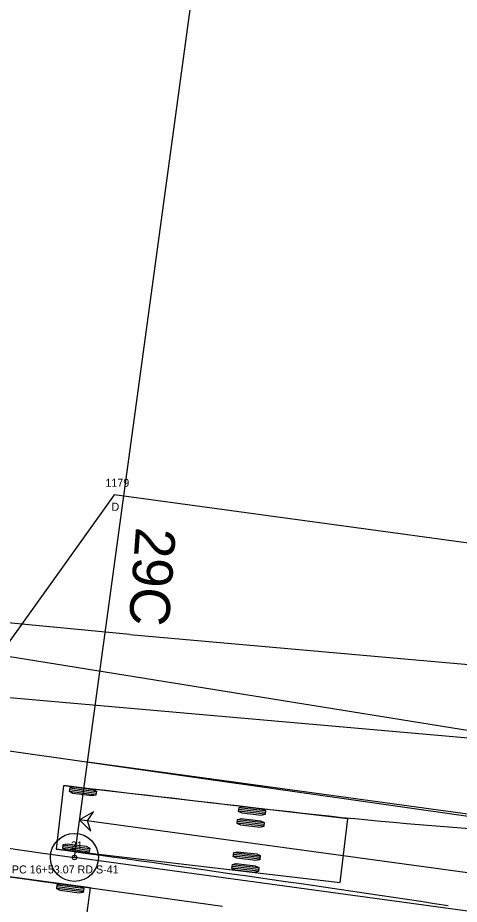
# Model space of a CAD drawing. Extents: x 1812113 to 1819860, y 1177290 to 1181185.
# Drawn here: x 1813531.1 to 1813586.4, y 1178765.6 to 1178876.4 of the extents above; entities that cross this region are included whole.
import ezdxf

# ---------------------------------------------------------------- set-up
doc = ezdxf.new("R2010")
doc.units = 0
for name, color, linetype in [('RD_EX_Driveway', 7, 'Continuous'), ('RD_EX_Driveway_txCode', 7, 'Continuous'), ('RD_EX_Road', 7, 'Continuous'), ('RD_EX_RW', 7, 'Continuous'), ('RD_HC_CL', 7, 'Continuous'), ('RD_HC_Data', 7, 'Continuous'), ('RD_HC_txCode', 7, 'Continuous'), ('RD_PD_ALT1_TrvlWay', 7, 'Continuous'), ('RD_PD_CstnLmt', 7, 'Continuous'), ('RD_Sketch5', 7, 'Continuous'), ('RD_Sketch9', 7, 'Continuous'), ('RD_SMD_Locator', 7, 'Continuous')]:
    doc.layers.add(name, color=color, linetype=linetype)

msp = doc.modelspace()

# ---------------------------------------------------------------- linework, layer by layer
at = {"layer": 'RD_EX_Driveway'}
for points in [[(1813615.6, 1178795.77), (1813617.78, 1178806.55), (1813543.17, 1178816.74), (1813525.31, 1178791.79)], [(1813638.42, 1178791.25), (1813630.13, 1178786.38), (1813613.34, 1178784.52), (1813588.43, 1178786.24), (1813525.31, 1178791.79), (1813522.62, 1178785.74)]]:
    msp.add_lwpolyline(points, dxfattribs=at)
at = {"layer": 'RD_EX_Road'}
msp.add_line((1813596.09, 1178775.31), (1813522.62, 1178785.74), dxfattribs=at)
at = {"layer": 'RD_EX_RW'}
msp.add_line((1813632.03, 1178780.07), (1813400.47, 1178817.38), dxfattribs=at)
at = {"layer": 'RD_HC_CL'}
msp.add_line((1813641.28, 1178757.34), (1813538.22, 1178771.42), dxfattribs=at)
msp.add_arc((1813766.93, 1180445.18), 1689.31, 243.58271, 262.2191, dxfattribs=at)
at = {"layer": 'RD_HC_Data'}
msp.add_line((1813538.22, 1178771.42), (1813553.17, 1178880.85), dxfattribs=at)
for radius in [3, 0.282]:
    msp.add_circle((1813538.22, 1178771.42), radius, dxfattribs=at)
at = {"layer": 'RD_PD_ALT1_TrvlWay'}
msp.add_line((1813598.75, 1178775.26), (1813539.84, 1178783.31), dxfattribs=at)
at = {"layer": 'RD_PD_CstnLmt'}
for q in [(1813496.03, 1178803.9), (1813594.99, 1178794.88)]:
    msp.add_line((1813545.13, 1178799.29), q, dxfattribs=at)
at = {"layer": 'RD_Sketch5'}
for p, q in [((1813540.22, 1178767.61), (1813504.75, 1178772.46)), ((1813539.31, 1178767.11), (1813536.01, 1178767.56)), ((1813539.34, 1178767.31), (1813536.04, 1178767.76)), ((1813539.37, 1178767.52), (1813536.07, 1178767.97)), ((1813539.14, 1178759.69), (1813540.22, 1178767.61)), ((1813540.22, 1178767.61), (1813540.22, 1178767.61))]:
    msp.add_line(p, q, dxfattribs=at)
msp.add_lwpolyline([(1813529.58, 1178769.07), (1813533.13, 1178768.58), (1813536.68, 1178768.1), (1813540.22, 1178767.61), (1813540.22, 1178767.61), (1813543.53, 1178767.16), (1813546.84, 1178766.71), (1813550.14, 1178766.26), (1813553.45, 1178765.81), (1813556.76, 1178765.35)], dxfattribs=at)
msp.add_lwpolyline([(1813539.38, 1178767.57), (1813539.3, 1178767.06), (1813538.82, 1178766.96), (1813536.44, 1178767.29), (1813536, 1178767.51), (1813536.07, 1178768.02), (1813536.56, 1178768.11), (1813538.93, 1178767.79)], close=True, dxfattribs=at)
at = {"layer": 'RD_Sketch9'}
for p, q in [((1813536.84, 1178780.39), (1813535.92, 1178772.44)), ((1813572.4, 1178776.24), (1813536.84, 1178780.39)), ((1813537.61, 1178779.7), (1813540.91, 1178779.25)), ((1813537.63, 1178779.91), (1813540.94, 1178779.46)), ((1813537.66, 1178780.12), (1813540.96, 1178779.66)), ((1813562.09, 1178777.02), (1813558.78, 1178777.41)), ((1813562.11, 1178777.23), (1813558.8, 1178777.62)), ((1813562.07, 1178776.82), (1813558.75, 1178777.2)), ((1813571.47, 1178768.3), (1813572.4, 1178776.24)), ((1813604.8, 1178767.12), (1813538.86, 1178776.13)), ((1813561.89, 1178775.33), (1813558.58, 1178775.71)), ((1813561.92, 1178775.53), (1813558.6, 1178775.92)), ((1813561.94, 1178775.74), (1813558.63, 1178776.13)), ((1813536.82, 1178773), (1813540.12, 1178772.55)), ((1813535.92, 1178772.44), (1813571.47, 1178768.3)), ((1813535.92, 1178772.44), (1813535.92, 1178772.44)), ((1813536.76, 1178772.59), (1813540.06, 1178772.14)), ((1813536.79, 1178772.79), (1813540.09, 1178772.34)), ((1813561.43, 1178771.4), (1813558.12, 1178771.78)), ((1813561.46, 1178771.6), (1813558.15, 1178771.99)), ((1813561.41, 1178771.19), (1813558.1, 1178771.58)), ((1813561.23, 1178769.7), (1813557.92, 1178770.09)), ((1813561.26, 1178769.91), (1813557.95, 1178770.29)), ((1813561.28, 1178770.11), (1813557.97, 1178770.5))]:
    msp.add_line(p, q, dxfattribs=at)
for points in [[(1813587.65, 1178775.01), (1813586.08, 1178775.12), (1813584.51, 1178775.23), (1813582.93, 1178775.36), (1813581.34, 1178775.49), (1813579.74, 1178775.62), (1813578.14, 1178775.77), (1813576.53, 1178775.91), (1813574.91, 1178776.07), (1813573.3, 1178776.23), (1813571.68, 1178776.39), (1813570.05, 1178776.56), (1813568.42, 1178776.74), (1813566.79, 1178776.92), (1813565.16, 1178777.1), (1813563.53, 1178777.28), (1813561.89, 1178777.47), (1813560.25, 1178777.66), (1813558.61, 1178777.85), (1813556.97, 1178778.04), (1813555.32, 1178778.23), (1813553.68, 1178778.42), (1813552.03, 1178778.62), (1813550.39, 1178778.81), (1813548.74, 1178779), (1813547.09, 1178779.19), (1813545.44, 1178779.39), (1813543.79, 1178779.58), (1813542.13, 1178779.77), (1813540.48, 1178779.96), (1813538.83, 1178780.16), (1813537.17, 1178780.35), (1813536.84, 1178780.39)], [(1813584.96, 1178765.38), (1813583.25, 1178765.64), (1813581.54, 1178765.9), (1813579.83, 1178766.16), (1813578.13, 1178766.41), (1813576.43, 1178766.66), (1813574.73, 1178766.91), (1813573.04, 1178767.16), (1813571.35, 1178767.41), (1813569.67, 1178767.66), (1813567.98, 1178767.9), (1813566.3, 1178768.15), (1813564.62, 1178768.39), (1813562.94, 1178768.63), (1813561.26, 1178768.87), (1813559.59, 1178769.11), (1813557.92, 1178769.35), (1813556.24, 1178769.59), (1813554.57, 1178769.83), (1813552.9, 1178770.06), (1813551.23, 1178770.3), (1813549.57, 1178770.53), (1813547.9, 1178770.77), (1813546.23, 1178771), (1813544.57, 1178771.24), (1813542.9, 1178771.47), (1813541.24, 1178771.7), (1813539.57, 1178771.93), (1813537.91, 1178772.17), (1813536.25, 1178772.4), (1813535.92, 1178772.44)]]:
    msp.add_lwpolyline(points, dxfattribs=at)
for points in [[(1813537.6, 1178779.65), (1813537.67, 1178780.17), (1813538.15, 1178780.26), (1813540.53, 1178779.93), (1813540.97, 1178779.72), (1813540.9, 1178779.2), (1813540.42, 1178779.11), (1813538.04, 1178779.43)], [(1813562.12, 1178777.28), (1813562.06, 1178776.77), (1813561.58, 1178776.66), (1813559.19, 1178776.94), (1813558.75, 1178777.15), (1813558.81, 1178777.67), (1813559.29, 1178777.77), (1813561.67, 1178777.49)], [(1813538.86, 1178776.13), (1813540.27, 1178774.7), (1813539.85, 1178775.99), (1813540.6, 1178777.12)], [(1813561.95, 1178775.79), (1813561.89, 1178775.28), (1813561.4, 1178775.18), (1813559.02, 1178775.45), (1813558.57, 1178775.66), (1813558.63, 1178776.18), (1813559.12, 1178776.28), (1813561.5, 1178776)], [(1813536.75, 1178772.54), (1813536.82, 1178773.05), (1813537.31, 1178773.14), (1813539.68, 1178772.82), (1813540.13, 1178772.6), (1813540.05, 1178772.08), (1813539.57, 1178771.99), (1813537.19, 1178772.32)], [(1813561.46, 1178771.65), (1813561.4, 1178771.14), (1813560.92, 1178771.04), (1813558.54, 1178771.31), (1813558.09, 1178771.52), (1813558.15, 1178772.04), (1813558.63, 1178772.14), (1813561.02, 1178771.86)], [(1813561.29, 1178770.16), (1813561.23, 1178769.65), (1813560.75, 1178769.55), (1813558.36, 1178769.82), (1813557.92, 1178770.03), (1813557.98, 1178770.55), (1813558.46, 1178770.65), (1813560.84, 1178770.37)]]:
    msp.add_lwpolyline(points, close=True, dxfattribs=at)
at = {"layer": 'RD_SMD_Locator'}
for centre in [(1813543.17, 1178816.74), (1813538.22, 1178771.42)]:
    msp.add_circle(centre, 0.001, dxfattribs=at)

# ---------------------------------------------------------------- texts
at = {"layer": 'RD_EX_Driveway_txCode'}
for s, p in [('1179', (1813542.1, 1178817.74)), ('D', (1813542.86, 1178814.74))]:
    msp.add_text(s, height=1, dxfattribs=at).set_placement(p)
at = {"layer": 'RD_HC_txCode'}
for s, p in [('21', (1813537.77, 1178772.42)), ('PC 16+53.07 RD S-41', (1813530.4, 1178769.42))]:
    msp.add_text(s, height=1, dxfattribs=at).set_placement(p)
at = {"layer": 'RD_PD_CstnLmt'}
msp.add_text('29C', height=5, rotation=265.7319, dxfattribs=at).set_placement((1813545.93, 1178812.77))

doc.saveas('drawing.dxf')
